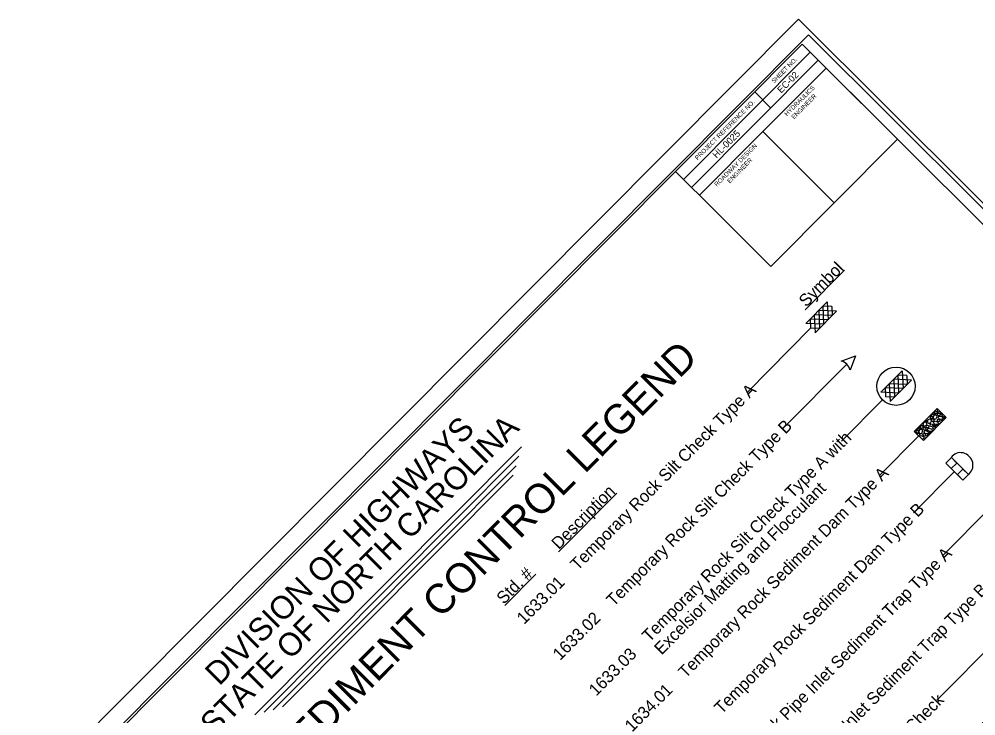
# Model space of a CAD drawing. Extents: x 1484932 to 1495672, y 495497 to 506262.
# Drawn here: x 1490730 to 1493934, y 503930 to 506262 of the extents above; entities that cross this region are included whole.
import ezdxf

# ---------------------------------------------------------------- set-up
doc = ezdxf.new("R2010")
doc.units = 0
for name, color, linetype in [('Scratch_Level_0', 7, 'Continuous'), ('Sheet Plot Border Inside CELL', 7, 'Continuous'), ('Sheet Plot Border Outside CELL', 7, 'Continuous')]:
    doc.layers.add(name, color=color, linetype=linetype)

msp = doc.modelspace()

# ---------------------------------------------------------------- linework, layer by layer
at = {"layer": 'Scratch_Level_0'}
for p, q in [((1492955, 505725.8), (1493379.2, 506151.7)), ((1492981.6, 505699.3), (1493405.8, 506125.2)), ((1493193.6, 506018.5), (1493246.8, 505965.5)), ((1493220.4, 505885.8), (1493459.8, 505647.4)), ((1492981.6, 505699.3), (1493008.3, 505672.8)), ((1493362.7, 505289.6), (1493494.6, 505422.2)), ((1493364.7, 505243.9), (1493436.2, 505315.8)), ((1493421.8, 505301.4), (1493424.2, 505241.2)), ((1493451.9, 505300.2), (1493421.8, 505301.4)), ((1493436.2, 505315.8), (1493439.1, 505256.3)), ((1493451.9, 505300.2), (1493453.1, 505270.2)), ((1493379.1, 505258.4), (1493380.3, 505228.3)), ((1493439.1, 505256.3), (1493379.1, 505258.4)), ((1493393, 505272.4), (1493396, 505212.9)), ((1493453.1, 505270.2), (1493393, 505272.4)), ((1493396, 505212.9), (1493467.5, 505284.7)), ((1493407.9, 505287.4), (1493410.4, 505227.3)), ((1493467.5, 505284.7), (1493407.9, 505287.4)), ((1493170.1, 505014.9), (1493380.3, 505228.3)), ((1493424.2, 505241.2), (1493364.7, 505243.9)), ((1493410.4, 505227.3), (1493380.3, 505228.3)), ((1493482.7, 505117.4), (1493531.1, 505135.8)), ((1493531.1, 505135.8), (1493512.7, 505087.5)), ((1493288.6, 504892.8), (1493501.8, 505107.3)), ((1493615.6, 505013.6), (1493687.2, 505085.5)), ((1493672.7, 505071.1), (1493675.1, 505010.9)), ((1493702.8, 505069.9), (1493672.7, 505071.1)), ((1493687.2, 505085.5), (1493690.1, 505026)), ((1493702.8, 505069.9), (1493704, 505039.9)), ((1493643.9, 505042.1), (1493646.9, 504982.6)), ((1493704, 505039.9), (1493643.9, 505042.1)), ((1493646.9, 504982.6), (1493718.4, 505054.4)), ((1493658.9, 505057.1), (1493661.3, 504997)), ((1493718.4, 505054.4), (1493658.9, 505057.1)), ((1493675.1, 505010.9), (1493615.6, 505013.6)), ((1493630, 505028.1), (1493631.3, 504998)), ((1493690.1, 505026), (1493630, 505028.1)), ((1493484, 504850.2), (1493621.4, 504988.2)), ((1493661.3, 504997), (1493631.3, 504998)), ((1493610.4, 504733.7), (1493742.9, 504867.2)), ((1491519.9, 503934.1), (1492412.9, 504830.8)), ((1491550.5, 503942.8), (1492403.5, 504799.3)), ((1493909.1, 504737.8), (1493852, 504794.7)), ((1493909.1, 504737.8), (1493852, 504794.7)), ((1491581.6, 503950.9), (1492394.6, 504767.3)), ((1493725, 504609.7), (1493862.2, 504747.8)), ((1493890.8, 504719.4), (1493833.7, 504776.3)), ((1493890.8, 504719.4), (1493833.7, 504776.3)), ((1491612.4, 503961), (1492384.6, 504736.4)), ((1493909.1, 504737.8), (1493890.8, 504719.4)), ((1493909.1, 504737.8), (1493890.8, 504719.4)), ((1492536, 504479.8), (1492731.3, 504675.9)), ((1493821.4, 504465.3), (1493982.8, 504627.8)), ((1492356.6, 504299.7), (1492460.4, 504404.1)), ((1493803.8, 503983.3), (1494214.6, 504397.5))]:
    msp.add_line(p, q, dxfattribs=at)
for points in [[(1493352.5, 506178.3), (1490172.1, 502984.8), (1492407.6, 500758.5), (1495587.9, 503952.1)], [(1492928.3, 505752.4), (1493352.5, 506178.3), (1493405.8, 506125.2), (1492981.6, 505699.3)], [(1493220.4, 505885.8), (1493432.4, 506098.7), (1493671.9, 505860.2), (1493459.9, 505647.3)], [(1493008.3, 505672.8), (1493220.4, 505885.8), (1493459.9, 505647.3), (1493247.8, 505434.3)], [(1493727.6, 504881.9), (1493804.8, 504959.4), (1493834.9, 504929.4), (1493758.3, 504852.5)], [(1493727.6, 504881.9), (1493804.8, 504959.4), (1493834.9, 504929.4), (1493758.3, 504852.5)], [(1493833.7, 504776.3), (1493852, 504794.7), (1493870, 504776.7), (1493851.7, 504758.3)], [(1493872.1, 504738), (1493890.5, 504756.4), (1493909.1, 504737.8), (1493890.8, 504719.4)]]:
    msp.add_lwpolyline(points, close=True, dxfattribs=at)
for points in [[(1493785.4, 504939.8), (1493785.5, 504937.5), (1493782.7, 504934.8), (1493780.9, 504935.4)], [(1493785.4, 504939.8), (1493785.5, 504937.5), (1493782.7, 504934.8), (1493780.9, 504935.4)], [(1493793.7, 504948.2), (1493794.3, 504946.5), (1493791.6, 504943.7), (1493789.8, 504944.3)], [(1493793.7, 504948.2), (1493794.3, 504946.5), (1493791.6, 504943.7), (1493789.8, 504944.3)], [(1493791.2, 504938.5), (1493790.5, 504940.2), (1493792.3, 504941.9), (1493794.5, 504941.8), (1493796.3, 504940), (1493795.8, 504938.3), (1493794.2, 504936.7), (1493793, 504936.7), (1493791.2, 504938.5)], [(1493791.2, 504938.5), (1493790.5, 504940.2), (1493792.3, 504941.9), (1493794.5, 504941.8), (1493796.3, 504940), (1493795.8, 504938.3), (1493794.2, 504936.7), (1493793, 504936.7), (1493791.2, 504938.5)], [(1493792.1, 504931), (1493794.2, 504935.5), (1493796.9, 504938.3), (1493799.8, 504937.6), (1493802.2, 504935.2), (1493803, 504931.1), (1493801.5, 504926), (1493798.7, 504923.2), (1493795.3, 504922.2), (1493792.9, 504924.6), (1493791.6, 504928.1), (1493792.1, 504931)], [(1493792.1, 504931), (1493794.2, 504935.5), (1493796.9, 504938.3), (1493799.8, 504937.6), (1493802.2, 504935.2), (1493803, 504931.1), (1493801.5, 504926), (1493798.7, 504923.2), (1493795.3, 504922.2), (1493792.9, 504924.6), (1493791.6, 504928.1), (1493792.1, 504931)], [(1493797.4, 504942.2), (1493796.6, 504946.3), (1493798.9, 504949.7), (1493802.3, 504949.6), (1493805.3, 504946.6), (1493804.8, 504943.8), (1493802.1, 504941), (1493799.7, 504941.1), (1493797.4, 504942.2)], [(1493797.4, 504942.2), (1493796.6, 504946.3), (1493798.9, 504949.7), (1493802.3, 504949.6), (1493805.3, 504946.6), (1493804.8, 504943.8), (1493802.1, 504941), (1493799.7, 504941.1), (1493797.4, 504942.2)], [(1493806.2, 504936.8), (1493805.5, 504940.9), (1493808.3, 504943.6), (1493811.8, 504943.5), (1493814.2, 504940), (1493814.3, 504937.6), (1493811.5, 504934.8), (1493809.2, 504934.9), (1493806.2, 504936.8)], [(1493806.2, 504936.8), (1493805.5, 504940.9), (1493808.3, 504943.6), (1493811.8, 504943.5), (1493814.2, 504940), (1493814.3, 504937.6), (1493811.5, 504934.8), (1493809.2, 504934.9), (1493806.2, 504936.8)], [(1493814.4, 504949.7), (1493812.2, 504947.5), (1493809.3, 504947.1), (1493806.9, 504949.4), (1493805.6, 504953), (1493806, 504955.8)], [(1493814.4, 504949.7), (1493812.2, 504947.5), (1493809.3, 504947.1), (1493806.9, 504949.4), (1493805.6, 504953), (1493806, 504955.8)], [(1493806, 504955.8), (1493807.2, 504957)], [(1493806, 504955.8), (1493807.2, 504957)], [(1493816.3, 504944.5), (1493815.6, 504948.5)], [(1493816.3, 504944.5), (1493815.6, 504948.5)], [(1493821.7, 504942.6), (1493821.7, 504942.6), (1493819.3, 504942.6), (1493816.3, 504944.5)], [(1493821.7, 504942.6), (1493821.7, 504942.6), (1493819.3, 504942.6), (1493816.3, 504944.5)], [(1493833.7, 504930.6), (1493833.7, 504930.6), (1493828.5, 504930.2), (1493823.2, 504932.2), (1493820.7, 504935.6), (1493820, 504938.6), (1493822.3, 504940.8), (1493823.4, 504940.8)], [(1493833.7, 504930.6), (1493833.7, 504930.6), (1493828.5, 504930.2), (1493823.2, 504932.2), (1493820.7, 504935.6), (1493820, 504938.6), (1493822.3, 504940.8), (1493823.4, 504940.8)], [(1493760.4, 504914.8), (1493761, 504914.2), (1493758.2, 504911.4), (1493757.6, 504911.9)], [(1493760.4, 504914.8), (1493761, 504914.2), (1493758.2, 504911.4), (1493757.6, 504911.9)], [(1493758.4, 504907.9), (1493759.9, 504911.9), (1493762.7, 504914.6), (1493765.6, 504914), (1493768, 504911.6), (1493769.3, 504906.9), (1493767.2, 504902.4), (1493764.5, 504899.6), (1493761.6, 504899.2), (1493758.6, 504901), (1493757.9, 504905), (1493758.4, 504907.9)], [(1493758.4, 504907.9), (1493759.9, 504911.9), (1493762.7, 504914.6), (1493765.6, 504914), (1493768, 504911.6), (1493769.3, 504906.9), (1493767.2, 504902.4), (1493764.5, 504899.6), (1493761.6, 504899.2), (1493758.6, 504901), (1493757.9, 504905), (1493758.4, 504907.9)], [(1493767.3, 504914.5), (1493766.7, 504917.4), (1493767.8, 504918.6), (1493770.1, 504918.4), (1493771.9, 504916.7), (1493771.4, 504914.9), (1493769.6, 504913.3), (1493768.5, 504913.3), (1493767.3, 504914.5)], [(1493767.3, 504914.5), (1493766.7, 504917.4), (1493767.8, 504918.6), (1493770.1, 504918.4), (1493771.9, 504916.7), (1493771.4, 504914.9), (1493769.6, 504913.3), (1493768.5, 504913.3), (1493767.3, 504914.5)], [(1493772.4, 504917.2), (1493774.5, 504921.8), (1493777.9, 504923.9), (1493780.8, 504924.4), (1493783.2, 504922.1), (1493784, 504916.8), (1493782.4, 504911.7), (1493779.6, 504908.8), (1493776.8, 504908.4), (1493773.8, 504910.3), (1493773.1, 504914.3), (1493773, 504917.7)], [(1493772.4, 504917.2), (1493774.5, 504921.8), (1493777.9, 504923.9), (1493780.8, 504924.4), (1493783.2, 504922.1), (1493784, 504916.8), (1493782.4, 504911.7), (1493779.6, 504908.8), (1493776.8, 504908.4), (1493773.8, 504910.3), (1493773.1, 504914.3), (1493773, 504917.7)], [(1493781.7, 504900.1), (1493781, 504904.2), (1493783.2, 504907.6), (1493787.2, 504906.9), (1493789.6, 504904.5), (1493789.8, 504901), (1493786.4, 504898.8), (1493784.1, 504898.9), (1493781.7, 504900.1)], [(1493781.7, 504900.1), (1493781, 504904.2), (1493783.2, 504907.6), (1493787.2, 504906.9), (1493789.6, 504904.5), (1493789.8, 504901), (1493786.4, 504898.8), (1493784.1, 504898.9), (1493781.7, 504900.1)], [(1493782.4, 504927.2), (1493781.6, 504931.3), (1493783.8, 504933.5), (1493787.9, 504934), (1493790.3, 504930.4), (1493789.9, 504927.6), (1493787.7, 504925.3), (1493785.3, 504925.4), (1493782.4, 504927.2)], [(1493782.4, 504927.2), (1493781.6, 504931.3), (1493783.8, 504933.5), (1493787.9, 504934), (1493790.3, 504930.4), (1493789.9, 504927.6), (1493787.7, 504925.3), (1493785.3, 504925.4), (1493782.4, 504927.2)], [(1493785.6, 504917.3), (1493785.5, 504921.9), (1493787.7, 504924.2), (1493791.2, 504924), (1493794.2, 504921.1), (1493793.7, 504918.2), (1493791, 504915.5), (1493788.6, 504915.5), (1493785.6, 504917.3)], [(1493785.6, 504917.3), (1493785.5, 504921.9), (1493787.7, 504924.2), (1493791.2, 504924), (1493794.2, 504921.1), (1493793.7, 504918.2), (1493791, 504915.5), (1493788.6, 504915.5), (1493785.6, 504917.3)], [(1493801.3, 504916.2), (1493805.4, 504914.3), (1493807.9, 504910.8), (1493808.5, 504907.9), (1493806.4, 504905.6), (1493801.2, 504905.2), (1493795.9, 504907.2), (1493792.9, 504910.1), (1493792.2, 504913.1), (1493794.4, 504915.3), (1493797.8, 504916.3), (1493800.8, 504915.6)], [(1493801.3, 504916.2), (1493805.4, 504914.3), (1493807.9, 504910.8), (1493808.5, 504907.9), (1493806.4, 504905.6), (1493801.2, 504905.2), (1493795.9, 504907.2), (1493792.9, 504910.1), (1493792.2, 504913.1), (1493794.4, 504915.3), (1493797.8, 504916.3), (1493800.8, 504915.6)], [(1493806.5, 504916.6), (1493805.2, 504920), (1493807.4, 504923.5), (1493811.4, 504922.8), (1493813.8, 504920.4), (1493814, 504916.8), (1493811.2, 504915.3), (1493808.3, 504914.8), (1493806.5, 504916.6)], [(1493806.5, 504916.6), (1493805.2, 504920), (1493807.4, 504923.5), (1493811.4, 504922.8), (1493813.8, 504920.4), (1493814, 504916.8), (1493811.2, 504915.3), (1493808.3, 504914.8), (1493806.5, 504916.6)], [(1493816.8, 504932.9), (1493820.9, 504931.1), (1493823.9, 504928), (1493824.6, 504925.2), (1493821.7, 504923.6), (1493817.2, 504922.5), (1493812.5, 504923.9), (1493808.9, 504927.4), (1493808.3, 504930.3), (1493810.5, 504932.6), (1493813.9, 504933.6), (1493816.8, 504932.9)], [(1493816.8, 504932.9), (1493820.9, 504931.1), (1493823.9, 504928), (1493824.6, 504925.2), (1493821.7, 504923.6), (1493817.2, 504922.5), (1493812.5, 504923.9), (1493808.9, 504927.4), (1493808.3, 504930.3), (1493810.5, 504932.6), (1493813.9, 504933.6), (1493816.8, 504932.9)], [(1493812.6, 504907.1), (1493813.1, 504910), (1493817, 504912.7), (1493817.6, 504912.2)], [(1493812.6, 504907.1), (1493813.1, 504910), (1493817, 504912.7), (1493817.6, 504912.2)], [(1493821, 504915.5), (1493820.3, 504918.5), (1493822.4, 504921.8), (1493825.9, 504921.7), (1493826.5, 504921.1)], [(1493821, 504915.5), (1493820.3, 504918.5), (1493822.4, 504921.8), (1493825.9, 504921.7), (1493826.5, 504921.1)], [(1493827.6, 504922.2), (1493826.9, 504925.1), (1493829.1, 504928.5), (1493833.1, 504927.7), (1493833.1, 504927.7)], [(1493827.6, 504922.2), (1493826.9, 504925.1), (1493829.1, 504928.5), (1493833.1, 504927.7), (1493833.1, 504927.7)], [(1493737.1, 504891.3), (1493737.7, 504889.6), (1493734.9, 504886.8), (1493733.2, 504887.5)], [(1493737.1, 504891.3), (1493737.7, 504889.6), (1493734.9, 504886.8), (1493733.2, 504887.5)], [(1493734.1, 504878.8), (1493733.9, 504883.4), (1493736.1, 504885.6), (1493739.7, 504885.5), (1493742.6, 504882.5), (1493742.1, 504879.7), (1493739.3, 504876.8), (1493737.1, 504877), (1493734.1, 504878.8)], [(1493734.1, 504878.8), (1493733.9, 504883.4), (1493736.1, 504885.6), (1493739.7, 504885.5), (1493742.6, 504882.5), (1493742.1, 504879.7), (1493739.3, 504876.8), (1493737.1, 504877), (1493734.1, 504878.8)], [(1493737.2, 504873.5), (1493737.2, 504873.5), (1493739.4, 504875.7), (1493743.4, 504876.2), (1493745.9, 504872.5), (1493745.4, 504869.7), (1493743.2, 504867.5), (1493743.2, 504867.5)], [(1493737.2, 504873.5), (1493737.2, 504873.5), (1493739.4, 504875.7), (1493743.4, 504876.2), (1493745.9, 504872.5), (1493745.4, 504869.7), (1493743.2, 504867.5), (1493743.2, 504867.5)], [(1493745.4, 504899.7), (1493746.1, 504897.9), (1493743.3, 504895.2), (1493741.5, 504895.8)], [(1493745.4, 504899.7), (1493746.1, 504897.9), (1493743.3, 504895.2), (1493741.5, 504895.8)], [(1493742.9, 504890), (1493742.8, 504892.3), (1493744.4, 504893.9), (1493746.8, 504893.9), (1493748.6, 504892.1), (1493747.6, 504889.8), (1493746.4, 504888.7), (1493744.7, 504888.2), (1493742.9, 504890)], [(1493742.9, 504890), (1493742.8, 504892.3), (1493744.4, 504893.9), (1493746.8, 504893.9), (1493748.6, 504892.1), (1493747.6, 504889.8), (1493746.4, 504888.7), (1493744.7, 504888.2), (1493742.9, 504890)], [(1493744.3, 504883), (1493745.8, 504887), (1493748.7, 504889.8), (1493752.2, 504889.6), (1493754.5, 504887.3), (1493754.7, 504882.6), (1493753.2, 504877.6), (1493750.4, 504874.7), (1493747.6, 504874.2), (1493745.1, 504876.7), (1493743.9, 504880.1), (1493744.3, 504883)], [(1493744.3, 504883), (1493745.8, 504887), (1493748.7, 504889.8), (1493752.2, 504889.6), (1493754.5, 504887.3), (1493754.7, 504882.6), (1493753.2, 504877.6), (1493750.4, 504874.7), (1493747.6, 504874.2), (1493745.1, 504876.7), (1493743.9, 504880.1), (1493744.3, 504883)], [(1493749.6, 504894.3), (1493748.9, 504898.5), (1493751, 504901.8), (1493754.6, 504901.7), (1493757, 504898.1), (1493757.2, 504894.7), (1493754.3, 504893.1), (1493751.5, 504892.6), (1493749.6, 504894.3)], [(1493749.6, 504894.3), (1493748.9, 504898.5), (1493751, 504901.8), (1493754.6, 504901.7), (1493757, 504898.1), (1493757.2, 504894.7), (1493754.3, 504893.1), (1493751.5, 504892.6), (1493749.6, 504894.3)], [(1493758.2, 504868.1), (1493756.8, 504872.7), (1493759.6, 504875.5), (1493763.7, 504874.8), (1493765.6, 504871.9), (1493766.2, 504869), (1493762.9, 504866.7), (1493760.5, 504866.9), (1493758.2, 504868.1)], [(1493758.2, 504868.1), (1493756.8, 504872.7), (1493759.6, 504875.5), (1493763.7, 504874.8), (1493765.6, 504871.9), (1493766.2, 504869), (1493762.9, 504866.7), (1493760.5, 504866.9), (1493758.2, 504868.1)], [(1493758.6, 504888.9), (1493757.8, 504892.9), (1493760, 504895.1), (1493763.4, 504895.1), (1493766.5, 504892), (1493766, 504889.2), (1493763.8, 504886.9), (1493760.9, 504886.4), (1493758.6, 504888.9)], [(1493758.6, 504888.9), (1493757.8, 504892.9), (1493760, 504895.1), (1493763.4, 504895.1), (1493766.5, 504892), (1493766, 504889.2), (1493763.8, 504886.9), (1493760.9, 504886.4), (1493758.6, 504888.9)], [(1493769.1, 504885), (1493773.7, 504882.6), (1493775.6, 504879.6), (1493776.3, 504876.7), (1493773.5, 504875.1), (1493769.5, 504874.6), (1493764.3, 504875.3), (1493761.2, 504879.6), (1493760.5, 504882.5), (1493762.7, 504884.7), (1493765.6, 504885.2), (1493769.1, 504885)], [(1493769.1, 504885), (1493773.7, 504882.6), (1493775.6, 504879.6), (1493776.3, 504876.7), (1493773.5, 504875.1), (1493769.5, 504874.6), (1493764.3, 504875.3), (1493761.2, 504879.6), (1493760.5, 504882.5), (1493762.7, 504884.7), (1493765.6, 504885.2), (1493769.1, 504885)], [(1493769.2, 504895.9), (1493767.3, 504900.1), (1493770.1, 504902.9), (1493774.7, 504902.7), (1493776.5, 504899.8), (1493776.7, 504896.3), (1493773.8, 504894.7), (1493771.1, 504894.2), (1493769.2, 504895.9)], [(1493769.2, 504895.9), (1493767.3, 504900.1), (1493770.1, 504902.9), (1493774.7, 504902.7), (1493776.5, 504899.8), (1493776.7, 504896.3), (1493773.8, 504894.7), (1493771.1, 504894.2), (1493769.2, 504895.9)], [(1493780.3, 504892.7), (1493784.4, 504890.8), (1493787.4, 504887.8), (1493788.1, 504884.9), (1493785.4, 504882.2), (1493780.7, 504882.3), (1493775.4, 504884.2), (1493772.4, 504887.2), (1493771.7, 504890.1), (1493773.9, 504892.3), (1493777.4, 504893.4), (1493780.3, 504892.7)], [(1493780.3, 504892.7), (1493784.4, 504890.8), (1493787.4, 504887.8), (1493788.1, 504884.9), (1493785.4, 504882.2), (1493780.7, 504882.3), (1493775.4, 504884.2), (1493772.4, 504887.2), (1493771.7, 504890.1), (1493773.9, 504892.3), (1493777.4, 504893.4), (1493780.3, 504892.7)], [(1493772.6, 504867), (1493772.5, 504870.4), (1493774.7, 504873.8), (1493778.2, 504873.7), (1493778.7, 504873.1)], [(1493772.6, 504867), (1493772.5, 504870.4), (1493774.7, 504873.8), (1493778.2, 504873.7), (1493778.7, 504873.1)], [(1493779.3, 504873.7), (1493779.2, 504877.2), (1493781.4, 504880.5), (1493785.4, 504879.8), (1493785.4, 504879.8)], [(1493779.3, 504873.7), (1493779.2, 504877.2), (1493781.4, 504880.5), (1493785.4, 504879.8), (1493785.4, 504879.8)], [(1493787.6, 504882), (1493787.1, 504882.6), (1493788.7, 504884.4), (1493789.9, 504884.3)], [(1493787.6, 504882), (1493787.1, 504882.6), (1493788.7, 504884.4), (1493789.9, 504884.3)], [(1493790.2, 504891.8), (1493789.4, 504895.8), (1493791.6, 504898), (1493795.7, 504898.5), (1493798.1, 504895), (1493797.7, 504892.1)], [(1493790.2, 504891.8), (1493789.4, 504895.8), (1493791.6, 504898), (1493795.7, 504898.5), (1493798.1, 504895), (1493797.7, 504892.1)], [(1493795.4, 504889.8), (1493794.8, 504889.3), (1493793.1, 504889.9), (1493790.2, 504891.8)], [(1493795.4, 504889.8), (1493794.8, 504889.3), (1493793.1, 504889.9), (1493790.2, 504891.8)], [(1493792.1, 504901), (1493792, 504903.3), (1493793.7, 504904.9), (1493795.4, 504905.4), (1493797.2, 504903.6), (1493797.3, 504901.3), (1493795.6, 504899.6), (1493793.9, 504900.3), (1493792.1, 504901)], [(1493792.1, 504901), (1493792, 504903.3), (1493793.7, 504904.9), (1493795.4, 504905.4), (1493797.2, 504903.6), (1493797.3, 504901.3), (1493795.6, 504899.6), (1493793.9, 504900.3), (1493792.1, 504901)], [(1493799.8, 504895.5), (1493798.5, 504900.1), (1493801.2, 504902.9), (1493804.7, 504902.8), (1493806.5, 504901)], [(1493799.8, 504895.5), (1493798.5, 504900.1), (1493801.2, 504902.9), (1493804.7, 504902.8), (1493806.5, 504901)], [(1493800.4, 504894.8), (1493799.8, 504895.5)], [(1493800.4, 504894.8), (1493799.8, 504895.5)], [(1493744.5, 504865.2), (1493746.7, 504867.4), (1493750, 504868.4), (1493753, 504867.7)], [(1493744.5, 504865.2), (1493746.7, 504867.4), (1493750, 504868.4), (1493753, 504867.7)], [(1493753, 504867.7), (1493757.1, 504865.8), (1493760.1, 504862.8), (1493760.2, 504860.6), (1493758.1, 504857.1), (1493752.8, 504856.8)], [(1493753, 504867.7), (1493757.1, 504865.8), (1493760.1, 504862.8), (1493760.2, 504860.6), (1493758.1, 504857.1), (1493752.8, 504856.8)], [(1493755.9, 504854.9), (1493757, 504854.9), (1493758.3, 504852.5)], [(1493755.9, 504854.9), (1493757, 504854.9), (1493758.3, 504852.5)], [(1493764.9, 504859.2), (1493766, 504861.5), (1493768.7, 504864.3), (1493769.9, 504864.2)], [(1493764.9, 504859.2), (1493766, 504861.5), (1493768.7, 504864.3), (1493769.9, 504864.2)]]:
    msp.add_lwpolyline(points, dxfattribs=at)
msp.add_circle((1493666.6, 505033.6), 64, dxfattribs=at)
for centre, major_axis, start_param, end_param in [((1493478.6, 505083.9), (25.2, -25.1), 0.944994, 2.196599), ((1493884.8, 504771.8), (-29.1, 29), 2.949905, 6.474869), ((1493884.8, 504771.8), (-29.1, 29), 2.949905, 6.474869)]:
    msp.add_ellipse(centre, major_axis=major_axis, ratio=0.927398, start_param=start_param, end_param=end_param, dxfattribs=at)
at = {"layer": 'Sheet Plot Border Inside CELL'}
msp.add_lwpolyline([(1492087.5, 500426.4), (1495619.8, 503973.4), (1493373.6, 506210.2), (1489841.3, 502663.3)], close=True, dxfattribs=at)
at = {"layer": 'Sheet Plot Border Outside CELL'}
msp.add_lwpolyline([(1492102.5, 500356.3), (1495671.9, 503940.6), (1493340.6, 506262.2), (1489771.2, 502678)], close=True, dxfattribs=at)

# ---------------------------------------------------------------- texts
at = {"layer": 'Scratch_Level_0'}
for s, height, rotation, p in [('SHEET NO.', 15.02, 45.1186, (1493258.6, 506046.6)), ('EC-02', 22.54, 45.1186, (1493282.3, 506012.9)), ('HYDRAULICS', 15.02, 45.1186, (1493301.8, 505936.4)), ('ENGINEER', 15.02, 45.1186, (1493325.1, 505926)), ('PROJECT REFERENCE NO.', 15.024, 45.1186, (1493002.2, 505789.6)), ('HL-0025', 22.54, 45.1186, (1493065.6, 505795)), ('ROADWAY DESIGN', 15.024, 45.1186, (1493066.9, 505700.6)), ('ENGINEER', 15.02, 45.1186, (1493110.2, 505711.9)), ('Symbol', 40.76, 45.1186, (1493365.8, 505296.4)), ('EROSION & SEDIMENT CONTROL LEGEND', 99.051, 45.1186, (1491086.8, 503194.8)), ('Temporary Rock Silt Check Type A', 40.761, 45.1186, (1492600.7, 504414.3)), ('STATE OF NORTH CAROLINA', 77.039, 45.1186, (1491383.9, 503859.9)), (' DIVISION OF HIGHWAYS', 77.039, 44.8885, (1491379.7, 504008.1)), ('Temporary Rock Silt Check Type B', 40.761, 45.1186, (1492721.3, 504294.3)), ('Temporary Rock Silt Check Type A with', 40.761, 45.1186, (1492840.7, 504175.3)), ('Temporary Rock Sediment Dam Type A', 40.777, 45.1186, (1492962.4, 504054.1)), ('Description', 40.761, 45.1186, (1492537.5, 504485)), ('Excelsior Matting and Flocculant', 40.761, 45.1186, (1492881.6, 504132.3)), ('Temporary Rock Sediment Dam Type B', 40.761, 45.1186, (1493082.6, 503933.9)), ('Rock Pipe Inlet Sediment Trap Type A', 40.704, 45.1186, (1493203.4, 503814.1)), ('Std. #', 40.76, 45.1186, (1492353.5, 504301.7)), ('1633.01', 40.71, 45.1186, (1492421.3, 504234.2)), ('Rock Pipe Inlet Sediment Trap Type B', 40.704, 45.1186, (1493322.9, 503693)), ('1633.02', 40.71, 45.1186, (1492541.8, 504114.2)), ('1633.03', 40.71, 45.1186, (1492662.4, 503994.1)), ('Excelsior Wattle Check with Flocculant', 40.761, 45.1186, (1493557.3, 503464.8)), ('1634.01', 40.71, 45.1186, (1492782.9, 503874.1)), ('Excelsior Wattle Check', 40.761, 45.1186, (1493435.1, 503583.3))]:
    msp.add_text(s, height=height, rotation=rotation, dxfattribs=at).set_placement(p)

doc.saveas('drawing.dxf')
